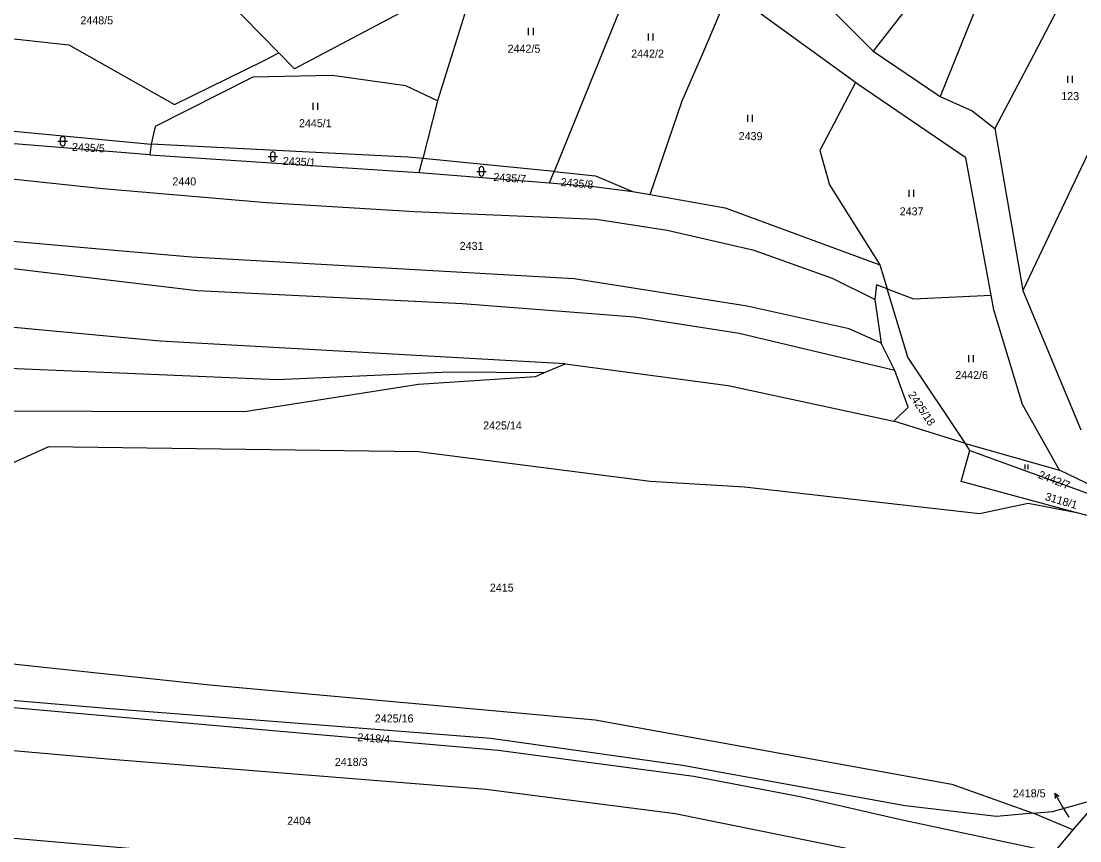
# Model space of a CAD drawing. Extents: x -776734 to -748832, y -1118122 to -976986.
# Drawn here: x -753707.7 to -753482.8, y -1115665 to -1115490.8 of the extents above; entities that cross this region are included whole.
import ezdxf

# ---------------------------------------------------------------- set-up
doc = ezdxf.new("R2010")
doc.units = 0
for name, color, linetype in [('KM_Hranice parcel', 7, 'Continuous'), ('KM_Parcelní čísla', 7, 'Continuous'), ('KM_Pop  PČ popisy', 7, 'Continuous'), ('KM_Značky kultur', 7, 'Continuous')]:
    doc.layers.add(name, color=color, linetype=linetype)

msp = doc.modelspace()

# ---------------------------------------------------------------- linework, layer by layer
at = {"layer": 'KM_Hranice parcel'}
for p, q in [((-753570.36, -1115463.2), (-753594.51, -1115522.79)), ((-753496.75, -1115467.75), (-753512.5, -1115506.85)), ((-753607.51, -1115470), (-753619.28, -1115507.74)), ((-753469.5, -1115494.37), (-753494.92, -1115548.02)), ((-753526.72, -1115497.21), (-753512.5, -1115506.85)), ((-753619.28, -1115507.74), (-753622.42, -1115520.03)), ((-753680.38, -1115519.25), (-753743.29, -1115514.04)), ((-753500.89, -1115513.62), (-753494.92, -1115548.02)), ((-753680.1, -1115516.93), (-753680.38, -1115519.25)), ((-753623.17, -1115522.99), (-753622.42, -1115520.03)), ((-753594.51, -1115522.79), (-753622.42, -1115520.03)), ((-753623.17, -1115522.99), (-753595.48, -1115525.19)), ((-753595.48, -1115525.19), (-753594.51, -1115522.79)), ((-753577.89, -1115527), (-753574.1, -1115527.68)), ((-753525.36, -1115542.59), (-753523.79, -1115547.71)), ((-753494.92, -1115548.02), (-753482.6, -1115577.61)), ((-753526.42, -1115549.95), (-753525.05, -1115559.2)), ((-753522.12, -1115565.01), (-753525.05, -1115559.2)), ((-753596.72, -1115565.54), (-753592.16, -1115563.6)), ((-753507.16, -1115580.58), (-753522.37, -1115575.79)), ((-753506.18, -1115582.06), (-753507.16, -1115580.58)), ((-753507.16, -1115580.58), (-753487.15, -1115586.2)), ((-753506.18, -1115582.06), (-753464.09, -1115597.4)), ((-753464.09, -1115597.4), (-753487.15, -1115586.2)), ((-753472.8, -1115598.14), (-753483.46, -1115595.27)), ((-753478.54, -1115655.91), (-753484.31, -1115662.65)), ((-753484.31, -1115662.65), (-753492.76, -1115659.07))]:
    msp.add_line(p, q, dxfattribs=at)
for points in [[(-753506.76, -1115468.51), (-753508.37, -1115473.5), (-753526.72, -1115497.21)], [(-753607.51, -1115470), (-753618.73, -1115473.69), (-753627.27, -1115489.14), (-753649.67, -1115500.96), (-753653.01, -1115497.54)], [(-753481.53, -1115476.51), (-753492.71, -1115498.03), (-753500.89, -1115513.62)], [(-753550.04, -1115477.8), (-753548.97, -1115481.08), (-753535.57, -1115488.33), (-753526.72, -1115497.21)], [(-753522.12, -1115565.01), (-753555.22, -1115557.19), (-753577.47, -1115553.7), (-753613.98, -1115550.85), (-753670.35, -1115548.08), (-753713.01, -1115543.03), (-753788.05, -1115537.23), (-753848.47, -1115533.73), (-753908.75, -1115530.78), (-753954.37, -1115526.36), (-754020.39, -1115519.01), (-754101.12, -1115512.11), (-754133.36, -1115510.11), (-754254.37, -1115500.16), (-754323.55, -1115493.63), (-754365.31, -1115485.02), (-754376.65, -1115481.22)], [(-753574.1, -1115527.68), (-753567.3, -1115507.72), (-753562.7, -1115497.21), (-753556.6, -1115482.75)], [(-753530.51, -1115503.85), (-753554.64, -1115486.34), (-753556.6, -1115482.75)], [(-753653.01, -1115497.54), (-753664.25, -1115486.02), (-753667.76, -1115484.95)], [(-753712.63, -1115488.4), (-753714.52, -1115493.99), (-753697.61, -1115495.83), (-753675.16, -1115508.55), (-753656.22, -1115499.23), (-753653.01, -1115497.54)], [(-753592.16, -1115563.6), (-753678.22, -1115558.81), (-753757.8, -1115551.36), (-753833.66, -1115545.49), (-753911.52, -1115540.62), (-754000.27, -1115531.45), (-754078.86, -1115524.44), (-754096.94, -1115523.16), (-754189.44, -1115515.84), (-754317.82, -1115504.53), (-754351.17, -1115500.24), (-754371.61, -1115494.94), (-754380.66, -1115490.83)], [(-753596.72, -1115565.54), (-753616.83, -1115565.42), (-753653.35, -1115567.05), (-753715.41, -1115564.41), (-753780.63, -1115557.58), (-753836.38, -1115554.93), (-753867.92, -1115552.69), (-753921.03, -1115547.5), (-754005.27, -1115538.95), (-754093, -1115531.54), (-754155.51, -1115526.97), (-754207.64, -1115521.38), (-754272.84, -1115515.86), (-754326.72, -1115511.78), (-754373.74, -1115503.78), (-754384.34, -1115499.27)], [(-753619.28, -1115507.74), (-753626, -1115504.56), (-753641.65, -1115502.36), (-753658.49, -1115502.72), (-753679.27, -1115513.21), (-753680.1, -1115516.93)], [(-753530.51, -1115503.85), (-753538.07, -1115518.33), (-753535.99, -1115525.59), (-753525.36, -1115542.59)], [(-753501.7, -1115549.02), (-753507.07, -1115519.89), (-753529.95, -1115504.26), (-753530.51, -1115503.85)], [(-753512.5, -1115506.85), (-753505.75, -1115509.89), (-753500.89, -1115513.62)], [(-753743.29, -1115514.04), (-753742.93, -1115511.04), (-753680.1, -1115516.93)], [(-753526.42, -1115549.95), (-753535.36, -1115545.51), (-753552.02, -1115539.52), (-753570.49, -1115535.33), (-753585.58, -1115532.95), (-753624.15, -1115531.31), (-753655.59, -1115529.42), (-753690.4, -1115526.47), (-753737.2, -1115521.52), (-753803.14, -1115515.14)], [(-753622.42, -1115520.03), (-753625.56, -1115519.72), (-753680.1, -1115516.93)], [(-753680.38, -1115519.25), (-753625.55, -1115522.8), (-753623.17, -1115522.99)], [(-753594.51, -1115522.79), (-753585.7, -1115523.66), (-753577.89, -1115527)], [(-753595.48, -1115525.19), (-753586.1, -1115525.94), (-753577.89, -1115527)], [(-753574.1, -1115527.68), (-753558.2, -1115530.51), (-753525.36, -1115542.59)], [(-753525.05, -1115559.2), (-753531.83, -1115556.18), (-753553.54, -1115551.35), (-753590.28, -1115545.58), (-753671.54, -1115540.97), (-753691.17, -1115539.25), (-753799.69, -1115529.65)], [(-753523.79, -1115547.71), (-753526.06, -1115546.85), (-753526.42, -1115549.95)], [(-753507.16, -1115580.58), (-753519.35, -1115562.18), (-753523.79, -1115547.71)], [(-753523.79, -1115547.71), (-753518.17, -1115549.84), (-753501.7, -1115549.02)], [(-753487.15, -1115586.2), (-753495.03, -1115572.29), (-753501.13, -1115552.13), (-753501.7, -1115549.02)], [(-753592.16, -1115563.6), (-753557.57, -1115568.21), (-753522.37, -1115575.79)], [(-753725.24, -1115573.63), (-753660.28, -1115573.74), (-753623.29, -1115567.95), (-753598.47, -1115566.29), (-753596.72, -1115565.54)], [(-753522.37, -1115575.79), (-753519.29, -1115572.83), (-753522.12, -1115565.01)], [(-753483.46, -1115595.27), (-753493.82, -1115593.31), (-753504.17, -1115595.47), (-753554.06, -1115589.84), (-753574.09, -1115588.62), (-753623.3, -1115582.33), (-753701.9, -1115581.25), (-753724.53, -1115591.43), (-753751.07, -1115605.21), (-753772.79, -1115620.62)], [(-753483.46, -1115595.27), (-753508.05, -1115588.63), (-753506.18, -1115582.06)], [(-753772.79, -1115620.62), (-753667.62, -1115631.84), (-753585.82, -1115639.22), (-753510.07, -1115652.94), (-753492.76, -1115659.07)], [(-753492.76, -1115659.07), (-753500.55, -1115659.77), (-753519.92, -1115657.49), (-753567.26, -1115648.96), (-753607.94, -1115643.19), (-753688.73, -1115636.9), (-753765.89, -1115630.41), (-753789.27, -1115628.39)], [(-753484.31, -1115662.65), (-753488.39, -1115667.42), (-753520.89, -1115660.48), (-753541.87, -1115655.7), (-753564.84, -1115651.29), (-753606.43, -1115645.75), (-753655.03, -1115641.55), (-753721.43, -1115635.62), (-753789.27, -1115628.39)], [(-753478.07, -1115679.5), (-753488.67, -1115675.54), (-753499.84, -1115672.92), (-753522.3, -1115668.66), (-753568.78, -1115659.22), (-753609.03, -1115654.03), (-753689.39, -1115647.62), (-753767.71, -1115640.65), (-753793.67, -1115638.32), (-753797.86, -1115637.97)], [(-753496.48, -1115694.03), (-753503.06, -1115691.4), (-753522.96, -1115684.89), (-753595.31, -1115673.72), (-753660.35, -1115668.68), (-753727.23, -1115662.91), (-753768.64, -1115658.56), (-753808.89, -1115651.76)], [(-753492.76, -1115659.07), (-753488.67, -1115658.7), (-753478.54, -1115655.91)]]:
    msp.add_lwpolyline(points, dxfattribs=at)
at = {"layer": 'KM_Pop  PČ popisy'}
for p, q in [((-753486.64, -1115657.43), (-753488.186, -1115654.858)), ((-753488.186, -1115654.858), (-753487.241, -1115655.458)), ((-753488.186, -1115654.858), (-753488.099, -1115655.974)), ((-753485.14, -1115659.94), (-753486.64, -1115657.43))]:
    msp.add_line(p, q, dxfattribs=at)
at = {"layer": 'KM_Značky kultur'}
for p, q in [((-753599.921, -1115493.77), (-753599.921, -1115492.27)), ((-753598.92, -1115493.77), (-753598.92, -1115492.27)), ((-753574.491, -1115494.91), (-753574.491, -1115493.41)), ((-753573.49, -1115494.91), (-753573.49, -1115493.41)), ((-753485.431, -1115503.93), (-753485.431, -1115502.43)), ((-753484.43, -1115503.93), (-753484.43, -1115502.43)), ((-753645.721, -1115509.69), (-753645.721, -1115508.19)), ((-753644.72, -1115509.69), (-753644.72, -1115508.19)), ((-753553.401, -1115512.24), (-753553.401, -1115510.74)), ((-753552.4, -1115512.24), (-753552.4, -1115510.74)), ((-753699.901, -1115516.331), (-753697.899, -1115516.331)), ((-753699.401, -1115515.831), (-753699.401, -1115516.832)), ((-753698.399, -1115516.832), (-753698.399, -1115515.831)), ((-753654.741, -1115519.081), (-753654.741, -1115520.082)), ((-753653.739, -1115520.082), (-753653.739, -1115519.081)), ((-753655.241, -1115519.581), (-753653.239, -1115519.581)), ((-753610.951, -1115522.731), (-753608.949, -1115522.731)), ((-753610.451, -1115522.231), (-753610.451, -1115523.232)), ((-753609.449, -1115523.232), (-753609.449, -1115522.231)), ((-753519.081, -1115528.14), (-753519.081, -1115526.64)), ((-753518.08, -1115528.14), (-753518.08, -1115526.64)), ((-753506.451, -1115563.3), (-753506.451, -1115561.8)), ((-753505.45, -1115563.3), (-753505.45, -1115561.8)), ((-753494.462, -1115586.02), (-753494.462, -1115585.015)), ((-753493.792, -1115586.02), (-753493.792, -1115585.015))]:
    msp.add_line(p, q, dxfattribs=at)
for centre, start, end in [((-753698.9, -1115515.8309), 0, 180), ((-753698.9, -1115516.8309), 180, 359.987886), ((-753654.24, -1115519.0809), 0, 180), ((-753654.24, -1115520.0809), 180, 359.987886), ((-753609.95, -1115522.2309), 0, 180), ((-753609.95, -1115523.2309), 180, 359.987886)]:
    msp.add_arc(centre, 0.5, start, end, dxfattribs=at)

# ---------------------------------------------------------------- texts
at = {"layer": 'KM_Parcelní čísla'}
for s, p in [('2448/5', (-753695.14, -1115491.49)), ('2442/5', (-753604.39, -1115497.53)), ('2442/2', (-753578.14, -1115498.57)), ('123', (-753486.79, -1115507.6)), ('2445/1', (-753648.71, -1115513.35)), ('2439', (-753555.31, -1115516.1)), ('2440', (-753675.6, -1115525.72)), ('2437', (-753521.11, -1115532.08)), ('2431', (-753614.57, -1115539.42)), ('2442/6', (-753509.31, -1115566.85)), ('2425/14', (-753609.59, -1115577.57)), ('2415', (-753608.16, -1115612.03)), ('2425/16', (-753632.6, -1115639.81)), ('2418/3', (-753641.09, -1115649.05)), ('2418/5', (-753497.075, -1115655.71)), ('2404', (-753651.21, -1115661.55))]:
    msp.add_text(s, height=1.7, dxfattribs=at).set_placement(p)
for s, rotation, p in [('2435/5', 357, (-753696.954, -1115518.358)), ('2435/1', 357, (-753652.174, -1115521.338)), ('2435/7', 356, (-753607.459, -1115524.747)), ('2435/8', 355, (-753593.184, -1115525.816)), ('2425/18', 304, (-753519.424, -1115570.175)), ('2442/7', 339, (-753491.824, -1115587.843)), ('3118/1', 344, (-753490.344, -1115592.557)), ('2418/4', 356, (-753636.349, -1115643.767))]:
    msp.add_text(s, height=1.7, rotation=rotation, dxfattribs=at).set_placement(p)

doc.saveas('drawing.dxf')
